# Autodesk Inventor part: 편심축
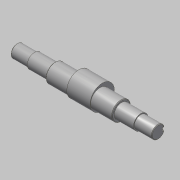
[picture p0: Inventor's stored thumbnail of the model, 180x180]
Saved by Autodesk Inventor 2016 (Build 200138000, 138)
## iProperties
Created: 2015-10
Part Number: 편심축
Document SubType Name: Modeling
Designer: mdu
Density: 7.86 g/cm^3
Material: 강철, 연강
Mass: 1327.93 g
Surface Area: 248.525 cm^2
Volume: 168.947 cm^3
Appearance: 강철
Author: mdu
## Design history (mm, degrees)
sketch "스케치1"
  geometry: L1 (-20.5, -41.331)-(-20.5, 32.669) reference; L2 (7.5, -30.031)-(7.5, 21.369) reference; L3 (135.5, -30.331)-(135.5, 21.669) reference; L4 (121.5, 21.369)-(121.5, -30.031) reference; L5 (184.5, -4.331)-(-57.5, -4.331); L6 (184.5, -4.331)-(184.5, 6.669); L7 (154.5, 8.169)-(121.5, 8.169); L8 (121.5, 8.169)-(121.5, 11.669); L9 (121.5, 11.669)-(7.5, 11.669); L10 (7.5, 11.669)-(7.5, 8.169); L11 (7.5, 8.169)-(-27.5, 8.169); L12 (-27.5, 8.169)-(-27.5, 6.669); L13 (-27.5, 6.669)-(-57.5, 6.669); L14 (-57.5, 6.669)-(-57.5, -4.331); L15 (154.5, 8.169)-(154.5, 6.669); L16 (154.5, 6.669)-(184.5, 6.669); C1 r 32.5 at (64.5, -4.331) reference; 1 further point
  constraints: 24 end point, 8 perpendicular, 5 point on line, 3 parallel, 2 collinear
  dimensions: "d1" = 25 diameter of L11 L5; "d2" = 32 diameter of L9 L5; "d3" = 22 diameter of L13 L5; "d4" = 35 distance of L10.end L11.end; "d5" = 30 distance of L12.end L13.end; "d15" = 33 distance of L7.start L7.end; "d26" = 30 distance of L15.end L6.end
revolve "회전1" sketch "스케치1" stored, may be unused: angle "d6" = 90 deg
node "작업 평면1"
sketch "스케치2"
  geometry: C1 r 16 at (0, 0) reference; C2 r 16 at (0, 0) reference; C3 r 20.75 at (0, 4); C4 r 16 at (0, 0) reference; 1 further point
  constraints: 1 centre point, 1 vertical alignment
  dimensions: "d8" = 41.5 diameter of C3; "d25" = 4 distance of C3.centre C1.centre
extrude "돌출1" join sketch "스케치2" stored distance "d9" = 40; taper "d10" = 0 deg
chamfer "모따기1" distance "d11" = 1; stored, may be unused: second distance "d12" = 2, angle "d13" = 45 deg
node "작업 평면2"
sketch "스케치3"
  geometry: L1 (-15, -10)-(-15, 10) reference; L2 (-15, 3)-(0, 3); L3 (0, -3)-(-15, -3); A1 r 3 centre (0, 0) between (0, -3) and (0, 3); 2 further points
  constraints: 4 end point, 2 perpendicular, 2 point on circle, 2 point on line, 2 tangent, 1 centre point, 1 horizontal alignment, 1 midpoint
  dimensions: "d16" = 18 dimension on A1 L1; "d17" = 6 distance between parallel lines of L3 L2
extrude "돌출2" cut sketch "스케치3" distance "d18" = 3.5; taper "d19" = 0 deg
node "작업 평면3"
node "솔리드1"
mirror "대칭1"
node "참조1"
node "참조2"
node "참조3"
node "참조4"
node "참조5"
node "투영된 루프1"
